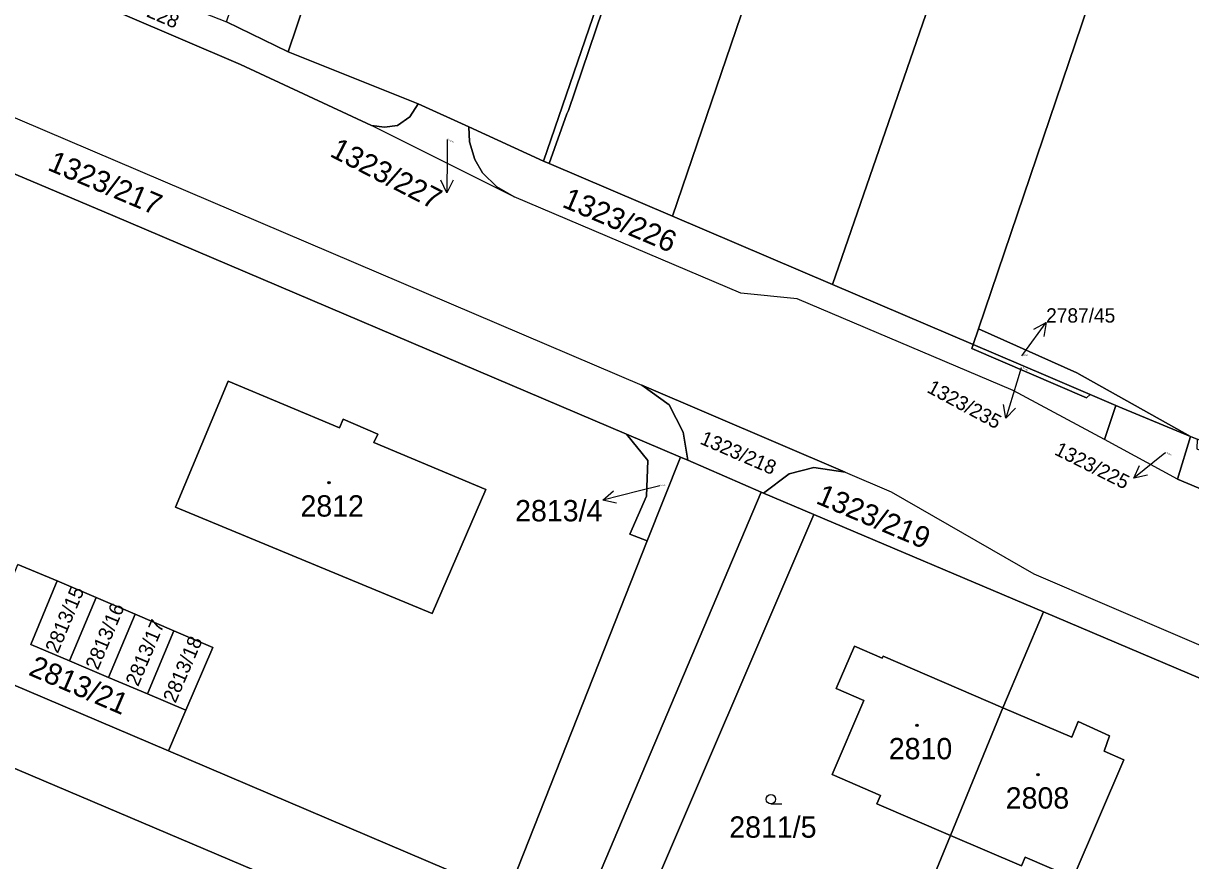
# Model space of a CAD drawing. Extents: x -596024 to -594475, y -1163820 to -1161957.
# Drawn here: x -594646.9 to -594553.9, y -1162306 to -1162239.3 of the extents above; entities that cross this region are included whole.
import ezdxf

# ---------------------------------------------------------------- set-up
doc = ezdxf.new("R2010")
doc.units = 0
for name, color, linetype in [('Level 1', 7, 'Continuous'), ('Level 4', 7, 'Continuous'), ('Level 5', 7, 'Continuous'), ('Level 57', 7, 'Continuous'), ('Level 60', 7, 'Continuous'), ('Vrstva 60', 7, 'Continuous')]:
    doc.layers.add(name, color=color, linetype=linetype)

msp = doc.modelspace()

# ---------------------------------------------------------------- linework, layer by layer
at = {"layer": 'Level 1'}
for points in [[(-594595.16, -1162254.67), (-594571.04, -1162183.94), (-594542.59, -1162099.77)], [(-594530.64, -1162108.54), (-594558.36, -1162190.54), (-594582.4, -1162260.11)], [(-594520.6, -1162116.35), (-594548.11, -1162196.83), (-594570.77, -1162263.66)], [(-594605.45, -1162250.28), (-594580.67, -1162178.16), (-594575.44, -1162162.74)], [(-594575.44, -1162162.74), (-594574, -1162163.22), (-594582.99, -1162189.81), (-594585.01, -1162192.07), (-594594.77, -1162220.59), (-594603.46, -1162246.24), (-594603.58, -1162246.52), (-594604.98, -1162250.48)], [(-594657.76, -1162230.53), (-594629.59, -1162242.59), (-594619.15, -1162247.45)], [(-594623.72, -1162235.42), (-594625.78, -1162241.57)], [(-594665.22, -1162239.43), (-594660.59, -1162241.27), (-594597.6, -1162268.15)], [(-594625.78, -1162241.57), (-594630.7, -1162239.18)], [(-594615.43, -1162245.72), (-594625.78, -1162241.57)], [(-594660.41, -1162245.9), (-594639.76, -1162254.61), (-594598.82, -1162272.04)], [(-594619.15, -1162247.45), (-594618.12, -1162247.58), (-594617.08, -1162247.44), (-594616.09, -1162246.75), (-594615.43, -1162245.72)], [(-594615.43, -1162245.72), (-594611.4, -1162247.56)], [(-594607.79, -1162253.13), (-594619.15, -1162247.45)], [(-594607.79, -1162253.13), (-594609.15, -1162252.32), (-594610.31, -1162251.21), (-594610.9, -1162250.15), (-594611.35, -1162248.75), (-594611.4, -1162247.56)], [(-594611.4, -1162247.56), (-594605.45, -1162250.28)], [(-594604.98, -1162250.48), (-594605.45, -1162250.28)], [(-594595.16, -1162254.67), (-594604.98, -1162250.48)], [(-594560.74, -1162272.48), (-594568, -1162268.56), (-594585.23, -1162261.27), (-594589.72, -1162260.8), (-594607.79, -1162253.13)], [(-594582.4, -1162260.11), (-594595.16, -1162254.67)], [(-594582.4, -1162260.11), (-594571.19, -1162264.9)], [(-594571.19, -1162264.9), (-594570.77, -1162263.66)], [(-594553.88, -1162272.22), (-594562.92, -1162267.15), (-594570.77, -1162263.66)], [(-594561.86, -1162268.88), (-594562.15, -1162269.14), (-594571.3, -1162265.21), (-594571.19, -1162264.9)], [(-594571.19, -1162264.9), (-594565.4, -1162267.37), (-594561.86, -1162268.88)], [(-594634.78, -1162277.85), (-594614.3, -1162286.32), (-594610.04, -1162276.44), (-594618.95, -1162272.7), (-594618.65, -1162272.03), (-594621.4, -1162270.84), (-594621.7, -1162271.55), (-594630.58, -1162267.82), (-594634.78, -1162277.85)], [(-594597.6, -1162268.15), (-594595.43, -1162269.7), (-594594.31, -1162271.88), (-594593.93, -1162274.12)], [(-594581.39, -1162275.07), (-594597.6, -1162268.15)], [(-594559.83, -1162269.75), (-594561.86, -1162268.88)], [(-594560.74, -1162272.48), (-594559.97, -1162270.16), (-594559.83, -1162269.75)], [(-594553.88, -1162272.22), (-594559.33, -1162269.96), (-594559.83, -1162269.75)], [(-594597.18, -1162280.54), (-594598.57, -1162280), (-594597.22, -1162276.99), (-594597.12, -1162274.15), (-594598.82, -1162272.04)], [(-594594.51, -1162273.87), (-594598.82, -1162272.04)], [(-594554.9, -1162275.64), (-594553.88, -1162272.22)], [(-594553.34, -1162272.45), (-594553.88, -1162272.22)], [(-594554.9, -1162275.64), (-594560.74, -1162272.48)], [(-594594.51, -1162273.87), (-594597.18, -1162280.54)], [(-594593.93, -1162274.12), (-594594.51, -1162273.87)], [(-594593.93, -1162274.12), (-594588.09, -1162276.66)], [(-594587.91, -1162276.73), (-594585.87, -1162275.19), (-594583.9, -1162274.71), (-594581.39, -1162275.07)], [(-594581.39, -1162275.07), (-594577.72, -1162276.64), (-594566.35, -1162283.18), (-594548.9, -1162290.65), (-594543.51, -1162291.25), (-594529.42, -1162297.02), (-594531.07, -1162300.87)], [(-594554.9, -1162275.64), (-594549.64, -1162277.84)], [(-594605.04, -1162316.67), (-594588.09, -1162276.66)], [(-594588.09, -1162276.66), (-594587.91, -1162276.73)], [(-594587.91, -1162276.73), (-594583.9, -1162278.44)], [(-594582.79, -1162317.01), (-594597.7, -1162310.66), (-594583.9, -1162278.44)], [(-594583.9, -1162278.44), (-594565.6, -1162286.2)], [(-594597.18, -1162280.54), (-594608.33, -1162308.78)], [(-594647.33, -1162282.42), (-594644.21, -1162283.74)], [(-594643.21, -1162290.11), (-594646.31, -1162288.8), (-594644.21, -1162283.74)], [(-594641.09, -1162285.07), (-594644.21, -1162283.74)], [(-594643.21, -1162290.11), (-594641.09, -1162285.07)], [(-594637.99, -1162286.39), (-594641.09, -1162285.07)], [(-594568.83, -1162293.84), (-594565.6, -1162286.2)], [(-594565.6, -1162286.2), (-594547.25, -1162293.99)], [(-594637.99, -1162286.39), (-594640.11, -1162291.42)], [(-594634.89, -1162287.71), (-594637.99, -1162286.39)], [(-594637.01, -1162292.73), (-594634.89, -1162287.71)], [(-594633.95, -1162294.03), (-594631.8, -1162289.03), (-594634.89, -1162287.71)], [(-594573.01, -1162304.02), (-594578.87, -1162301.51), (-594578.57, -1162300.83), (-594582.43, -1162299.17), (-594579.9, -1162293.27), (-594582.11, -1162292.32), (-594580.66, -1162288.93), (-594578.45, -1162289.89), (-594578.38, -1162289.73), (-594568.83, -1162293.84)], [(-594650.76, -1162290.72), (-594635.34, -1162297.28)], [(-594643.21, -1162290.11), (-594640.11, -1162291.42)], [(-594640.11, -1162291.42), (-594637.01, -1162292.73)], [(-594637.01, -1162292.73), (-594633.95, -1162294.03)], [(-594633.95, -1162294.03), (-594635.34, -1162297.28)], [(-594568.83, -1162293.84), (-594563.33, -1162296.2), (-594562.83, -1162294.95), (-594560.32, -1162296.08), (-594560.75, -1162297.31), (-594559.18, -1162297.98), (-594563.23, -1162307.4), (-594567.04, -1162305.76), (-594567.34, -1162306.45), (-594573.01, -1162304.02)], [(-594568.83, -1162293.84), (-594573.01, -1162304.02)], [(-594635.34, -1162297.28), (-594608.33, -1162308.78)], [(-594648.27, -1162298.38), (-594610.68, -1162314.35)], [(-594573.01, -1162304.02), (-594577.22, -1162314.27)]]:
    msp.add_lwpolyline(points, dxfattribs=at)
at = {"layer": 'Level 5'}
msp.add_line((-594587.32, -1162301.51), (-594586.445, -1162301.51), dxfattribs=at)
for centre, radius in [((-594622.53, -1162275.91), 0.09), ((-594622.53, -1162275.91), 0.0521), ((-594575.68, -1162295.25), 0.09), ((-594575.68, -1162295.25), 0.0521), ((-594566.03, -1162299.18), 0.09), ((-594566.03, -1162299.18), 0.0521), ((-594587.32, -1162301.135), 0.375)]:
    msp.add_circle(centre, radius, dxfattribs=at)
at = {"layer": 'Level 57'}
for p, q in [((-594613.12, -1162248.57), (-594613.126, -1162249.81)), ((-594613.126, -1162249.81), (-594613.14, -1162252.81)), ((-594567.148, -1162265.574), (-594565.38, -1162263.15)), ((-594567.32, -1162265.81), (-594567.148, -1162265.574)), ((-594567.37, -1162266.75), (-594567.724, -1162267.911)), ((-594567.724, -1162267.911), (-594568.6, -1162270.78)), ((-594556.06, -1162273.673), (-594558.4, -1162275.55)), ((-594555.87, -1162273.52), (-594556.06, -1162273.673)), ((-594597.798, -1162276.567), (-594600.71, -1162277.29)), ((-594596.16, -1162276.16), (-594597.798, -1162276.567))]:
    msp.add_line(p, q, dxfattribs=at)
for points in [[(-594612.635, -1162251.812), (-594613.14, -1162252.81), (-594613.635, -1162251.808)], [(-594566.373, -1162263.663), (-594565.38, -1162263.15), (-594565.566, -1162264.253)], [(-594567.83, -1162269.97), (-594568.6, -1162270.78), (-594568.786, -1162269.678)], [(-594557.307, -1162275.315), (-594558.4, -1162275.55), (-594557.933, -1162274.535)], [(-594599.619, -1162277.534), (-594600.71, -1162277.29), (-594599.86, -1162276.564)]]:
    msp.add_lwpolyline(points, dxfattribs=at)
at = {"layer": 'Level 60'}
for points in [[(-594571.04, -1162183.94), (-594595.16, -1162254.67), (-594604.98, -1162250.48), (-594603.58, -1162246.52), (-594603.46, -1162246.24), (-594594.77, -1162220.59), (-594585.01, -1162192.07), (-594582.99, -1162189.81), (-594574, -1162163.22), (-594575.44, -1162162.74), (-594551.69, -1162092.73), (-594542.59, -1162099.77)], [(-594542.59, -1162099.77), (-594530.64, -1162108.54), (-594558.36, -1162190.54), (-594582.4, -1162260.11), (-594595.16, -1162254.67), (-594571.04, -1162183.94)], [(-594530.64, -1162108.54), (-594520.6, -1162116.35), (-594548.11, -1162196.83), (-594570.77, -1162263.66), (-594571.19, -1162264.9), (-594582.4, -1162260.11), (-594558.36, -1162190.54)], [(-594520.6, -1162116.35), (-594514.49, -1162121.58), (-594509.36, -1162125.97), (-594503.99, -1162130.57), (-594530.33, -1162206.94), (-594537.56, -1162227.73), (-594553.14, -1162272.53), (-594553.34, -1162272.45), (-594553.88, -1162272.22), (-594562.92, -1162267.15), (-594570.77, -1162263.66), (-594548.11, -1162196.83)], [(-594596.99, -1162155.53), (-594575.44, -1162162.74), (-594580.67, -1162178.16), (-594605.45, -1162250.28), (-594611.4, -1162247.56), (-594615.43, -1162245.72), (-594625.78, -1162241.57), (-594623.72, -1162235.42), (-594616.95, -1162215.18), (-594618.95, -1162214.46), (-594618.12, -1162212), (-594607.2, -1162215.76), (-594608.05, -1162218.17), (-594607.65, -1162218.33), (-594590.52, -1162168.26), (-594601.83, -1162164.39), (-594598.65, -1162154.97)], [(-594582.99, -1162189.81), (-594585.01, -1162192.07), (-594594.77, -1162220.59), (-594603.46, -1162246.24), (-594603.58, -1162246.52), (-594604.98, -1162250.48), (-594605.45, -1162250.28), (-594580.67, -1162178.16), (-594575.44, -1162162.74), (-594574, -1162163.22)], [(-594630.7, -1162239.18), (-594625.78, -1162241.57), (-594615.43, -1162245.72), (-594616.09, -1162246.75), (-594617.08, -1162247.44), (-594618.12, -1162247.58), (-594619.15, -1162247.45), (-594629.59, -1162242.59), (-594657.76, -1162230.53), (-594659.93, -1162229.37), (-594661.48, -1162227.78), (-594662.11, -1162226.33), (-594662.13, -1162226.07), (-594655, -1162228.9), (-594646.47, -1162232.49), (-594640.6, -1162235.06), (-594634.99, -1162237.5)], [(-594625.78, -1162241.57), (-594630.7, -1162239.18), (-594628.68, -1162233.25), (-594623.72, -1162235.42)], [(-594677.27, -1162238.66), (-594676.95, -1162238.57), (-594673, -1162237.9), (-594668.99, -1162238.31), (-594665.22, -1162239.43), (-594660.59, -1162241.27), (-594597.6, -1162268.15), (-594595.43, -1162269.7), (-594594.31, -1162271.88), (-594593.93, -1162274.12), (-594594.51, -1162273.87), (-594598.82, -1162272.04), (-594639.76, -1162254.61), (-594660.41, -1162245.9), (-594672.61, -1162240.67)], [(-594619.15, -1162247.45), (-594618.12, -1162247.58), (-594617.08, -1162247.44), (-594616.09, -1162246.75), (-594615.43, -1162245.72), (-594611.4, -1162247.56), (-594611.35, -1162248.75), (-594610.9, -1162250.15), (-594610.31, -1162251.21), (-594609.15, -1162252.32), (-594607.79, -1162253.13)], [(-594595.16, -1162254.67), (-594582.4, -1162260.11), (-594571.19, -1162264.9), (-594571.3, -1162265.21), (-594562.15, -1162269.14), (-594561.86, -1162268.88), (-594559.83, -1162269.75), (-594559.97, -1162270.16), (-594560.74, -1162272.48), (-594568, -1162268.56), (-594585.23, -1162261.27), (-594589.72, -1162260.8), (-594607.79, -1162253.13), (-594609.15, -1162252.32), (-594610.31, -1162251.21), (-594610.9, -1162250.15), (-594611.35, -1162248.75), (-594611.4, -1162247.56), (-594605.45, -1162250.28), (-594604.98, -1162250.48)], [(-594565.4, -1162267.37), (-594571.19, -1162264.9), (-594570.77, -1162263.66), (-594562.92, -1162267.15), (-594553.88, -1162272.22), (-594559.33, -1162269.96), (-594559.83, -1162269.75), (-594561.86, -1162268.88)], [(-594571.19, -1162264.9), (-594565.4, -1162267.37), (-594561.86, -1162268.88), (-594562.15, -1162269.14), (-594571.3, -1162265.21)], [(-594634.78, -1162277.85), (-594614.3, -1162286.32), (-594610.04, -1162276.44), (-594618.95, -1162272.7), (-594618.65, -1162272.03), (-594621.4, -1162270.84), (-594621.7, -1162271.55), (-594630.58, -1162267.82)], [(-594614.3, -1162286.32), (-594634.78, -1162277.85), (-594630.58, -1162267.82), (-594621.7, -1162271.55), (-594621.4, -1162270.84), (-594618.65, -1162272.03), (-594618.95, -1162272.7), (-594610.04, -1162276.44)], [(-594595.43, -1162269.7), (-594597.6, -1162268.15), (-594581.39, -1162275.07), (-594583.9, -1162274.71), (-594585.87, -1162275.19), (-594587.91, -1162276.73), (-594588.09, -1162276.66), (-594593.93, -1162274.12), (-594594.31, -1162271.88)], [(-594554.9, -1162275.64), (-594560.74, -1162272.48), (-594559.97, -1162270.16), (-594559.83, -1162269.75), (-594559.33, -1162269.96), (-594553.88, -1162272.22)], [(-594597.18, -1162280.54), (-594598.57, -1162280), (-594597.22, -1162276.99), (-594597.12, -1162274.15), (-594598.82, -1162272.04), (-594594.51, -1162273.87)], [(-594547.72, -1162278.32), (-594549.64, -1162277.84), (-594554.9, -1162275.64), (-594553.88, -1162272.22), (-594553.34, -1162272.45), (-594553.37, -1162273.2), (-594546.04, -1162276.31), (-594545.63, -1162275.65), (-594542.31, -1162277.03), (-594542.57, -1162277.27), (-594544.02, -1162277.82), (-594545.75, -1162278.28)], [(-594693.16, -1162272.69), (-594686.42, -1162275.54), (-594650.76, -1162290.72), (-594635.34, -1162297.28), (-594608.33, -1162308.78), (-594610.68, -1162314.35), (-594648.27, -1162298.38), (-594695.58, -1162278.29)], [(-594675.58, -1162445.23), (-594673.97, -1162440.12), (-594671.23, -1162441.24), (-594667.96, -1162441.13), (-594665.34, -1162439.76), (-594663.46, -1162437.42), (-594660.9, -1162432.59), (-594651.34, -1162409.99), (-594643.71, -1162392.05), (-594610.68, -1162314.35), (-594608.33, -1162308.78), (-594597.18, -1162280.54), (-594594.51, -1162273.87), (-594593.93, -1162274.12), (-594588.09, -1162276.66), (-594605.04, -1162316.67), (-594625.82, -1162365.52), (-594637.27, -1162392.22), (-594652.18, -1162427.42), (-594655.04, -1162433.78), (-594664.15, -1162454.04), (-594676.67, -1162448.71)], [(-594587.91, -1162276.73), (-594585.87, -1162275.19), (-594583.9, -1162274.71), (-594581.39, -1162275.07), (-594577.72, -1162276.64), (-594566.35, -1162283.18), (-594548.9, -1162290.65), (-594543.51, -1162291.25), (-594529.42, -1162297.02), (-594531.07, -1162300.87), (-594547.25, -1162293.99), (-594565.6, -1162286.2), (-594583.9, -1162278.44)], [(-594535.15, -1162337.3), (-594531.45, -1162338.83), (-594503.84, -1162350.54), (-594505.06, -1162353.4), (-594527.23, -1162343.87), (-594529.36, -1162348.89), (-594605.04, -1162316.67), (-594588.09, -1162276.66), (-594587.91, -1162276.73), (-594583.9, -1162278.44), (-594597.7, -1162310.66), (-594582.79, -1162317.01), (-594579.01, -1162318.62), (-594575.31, -1162320.2), (-594560.65, -1162326.44)], [(-594582.79, -1162317.01), (-594597.7, -1162310.66), (-594583.9, -1162278.44), (-594565.6, -1162286.2), (-594568.83, -1162293.84), (-594578.38, -1162289.73), (-594578.45, -1162289.89), (-594580.66, -1162288.93), (-594582.11, -1162292.32), (-594579.9, -1162293.27), (-594582.43, -1162299.17), (-594578.57, -1162300.83), (-594578.87, -1162301.51), (-594573.01, -1162304.02), (-594577.22, -1162314.27), (-594580.99, -1162312.66)], [(-594646.31, -1162288.8), (-594643.21, -1162290.11), (-594640.11, -1162291.42), (-594637.01, -1162292.73), (-594633.95, -1162294.03), (-594635.34, -1162297.28), (-594650.76, -1162290.72), (-594649.42, -1162287.48), (-594647.33, -1162282.42), (-594644.21, -1162283.74)], [(-594644.21, -1162283.74), (-594641.09, -1162285.07), (-594643.21, -1162290.11), (-594646.31, -1162288.8)], [(-594641.09, -1162285.07), (-594637.99, -1162286.39), (-594640.11, -1162291.42), (-594643.21, -1162290.11)], [(-594560.65, -1162326.44), (-594575.31, -1162320.2), (-594573.46, -1162315.87), (-594577.22, -1162314.27), (-594573.01, -1162304.02), (-594567.34, -1162306.45), (-594567.04, -1162305.76), (-594563.23, -1162307.4), (-594559.18, -1162297.98), (-594560.75, -1162297.31), (-594560.32, -1162296.08), (-594562.83, -1162294.95), (-594563.33, -1162296.2), (-594568.83, -1162293.84), (-594565.6, -1162286.2), (-594547.25, -1162293.99)], [(-594637.99, -1162286.39), (-594634.89, -1162287.71), (-594637.01, -1162292.73), (-594640.11, -1162291.42)], [(-594631.8, -1162289.03), (-594633.95, -1162294.03), (-594637.01, -1162292.73), (-594634.89, -1162287.71)], [(-594568.83, -1162293.84), (-594573.01, -1162304.02), (-594578.87, -1162301.51), (-594578.57, -1162300.83), (-594582.43, -1162299.17), (-594579.9, -1162293.27), (-594582.11, -1162292.32), (-594580.66, -1162288.93), (-594578.45, -1162289.89), (-594578.38, -1162289.73)], [(-594573.01, -1162304.02), (-594568.83, -1162293.84), (-594563.33, -1162296.2), (-594562.83, -1162294.95), (-594560.32, -1162296.08), (-594560.75, -1162297.31), (-594559.18, -1162297.98), (-594563.23, -1162307.4), (-594567.04, -1162305.76), (-594567.34, -1162306.45)], [(-594648.27, -1162298.38), (-594610.68, -1162314.35), (-594643.71, -1162392.05), (-594645.86, -1162393.52), (-594649.29, -1162394.03), (-594683.2, -1162380.56)]]:
    msp.add_lwpolyline(points, close=True, dxfattribs=at)
msp.add_lwpolyline([(-594660.41, -1162245.9), (-594639.76, -1162254.61), (-594598.82, -1162272.04), (-594597.12, -1162274.15), (-594597.22, -1162276.99), (-594598.57, -1162280), (-594597.18, -1162280.54), (-594608.33, -1162308.78), (-594635.34, -1162297.28), (-594633.95, -1162294.03), (-594631.8, -1162289.03), (-594634.89, -1162287.71), (-594637.99, -1162286.39), (-594641.09, -1162285.07), (-594644.21, -1162283.74), (-594647.33, -1162282.42)], dxfattribs=at)
at = {"layer": 'Vrstva 60'}
for points in [[(-594475.47, -1162324.605), (-594475.47, -1162304.874), (-594478.52, -1162303.57), (-594489.02, -1162299.2), (-594496.7, -1162296.01), (-594500.16, -1162294.57), (-594502.42, -1162293.63), (-594508.12, -1162291.26), (-594509.45, -1162290.71), (-594514.57, -1162288.57), (-594517.89, -1162287.2), (-594518.19, -1162288.02), (-594519.37, -1162290.84), (-594525.36, -1162288.28), (-594549.64, -1162277.84), (-594554.9, -1162275.64), (-594560.74, -1162272.48), (-594568, -1162268.56), (-594585.23, -1162261.27), (-594589.72, -1162260.8), (-594607.79, -1162253.13), (-594619.15, -1162247.45), (-594629.59, -1162242.59), (-594657.76, -1162230.53)], [(-594660.59, -1162241.27), (-594597.6, -1162268.15), (-594581.39, -1162275.07), (-594577.72, -1162276.64), (-594566.35, -1162283.18), (-594548.9, -1162290.65), (-594543.51, -1162291.25), (-594529.42, -1162297.02), (-594531.07, -1162300.87), (-594490.06, -1162318.31)]]:
    msp.add_lwpolyline(points, dxfattribs=at)

# ---------------------------------------------------------------- texts
at = {"layer": 'Level 4'}
for s, height, rotation, p in [('1323/228', 1.14, 336.82347, (-594640.65, -1162237.24)), ('1323/227', 0.1, 332.65017, (-594613.12, -1162248.57)), ('1323/217', 1.7, 337.13037, (-594645.05, -1162250.96)), ('1323/226', 1.7, 337.00068, (-594604.04, -1162253.9)), ('1323/235', 0.1, 331.73604, (-594567.37, -1162266.75)), ('1323/218', 1.14, 336.56067, (-594593.04, -1162272.78)), ('1323/225', 0.1, 333.43497, (-594555.87, -1162273.52)), ('1323/219', 1.7, 336.94227, (-594583.81, -1162277.52)), ('2813/15', 1.14, 67.18671, (-594644.15, -1162289.57)), ('2813/16', 1.14, 67.14594, (-594640.95, -1162290.9)), ('2813/17', 1.14, 67.10517, (-594637.75, -1162292.21)), ('2813/18', 1.14, 66.7323, (-594634.77, -1162293.53)), ('2813/21', 1.7, 336.71034, (-594646.567, -1162291.193))]:
    msp.add_text(s, height=height, rotation=rotation, dxfattribs=at).set_placement(p)
for s, height, p in [('2787/45', 0.1, (-594567.32, -1162265.81)), ('2813/4', 0.1, (-594596.16, -1162276.16)), ('2812', 1.7, (-594624.81, -1162278.61)), ('2810', 1.7, (-594577.92, -1162297.95)), ('2808', 1.7, (-594568.6, -1162301.88)), ('2811/5', 1.7, (-594590.633, -1162304.2))]:
    msp.add_text(s, height=height, dxfattribs=at).set_placement(p)
at = {"layer": 'Level 57'}
for s, height, rotation, p in [('1323/227', 1.7, 332.65017, (-594622.554, -1162249.854)), ('1323/235', 1.14, 331.73604, (-594574.951, -1162268.66)), ('1323/225', 1.14, 333.43497, (-594564.797, -1162273.626))]:
    msp.add_text(s, height=height, rotation=rotation, dxfattribs=at).set_placement(p)
for s, height, p in [('2787/45', 1.14, (-594565.38, -1162263.15)), ('2813/4', 1.7, (-594607.702, -1162278.99))]:
    msp.add_text(s, height=height, dxfattribs=at).set_placement(p)

doc.saveas('drawing.dxf')
